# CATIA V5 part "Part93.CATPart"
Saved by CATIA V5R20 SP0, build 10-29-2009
Part number: IA 3217SF
Revision: ANY
Definition: UNKNOWN
Nomenclature: IA 3217SF
Source: Unknown
Bounding box of the stored display mesh (mm): x -1.6 to 1.6, y -8.75 to 8.2, z -1.6 to 1.6
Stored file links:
  C:\Users\Utente\Desktop\IO LAVORO\3D X SITO CF\CUMSA\3D files FA\FA 063200\Part93.CATPart

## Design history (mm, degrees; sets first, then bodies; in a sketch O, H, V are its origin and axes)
Body1 "Cortar-Extruir2" (main body)
  Solid1: solid without history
